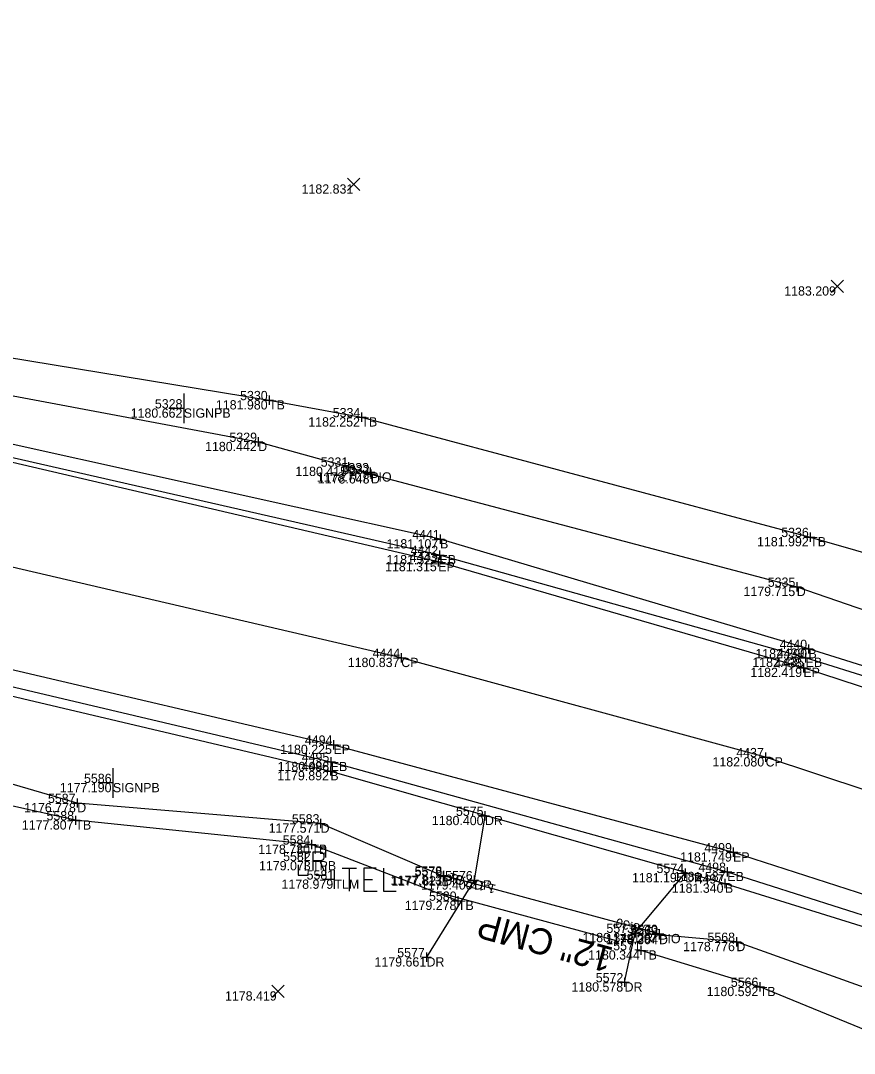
# Model space of a CAD drawing. Extents: x 2044996 to 2050343, y 455232 to 458054.
# Drawn here: x 2046920.1 to 2047010.1, y 457200 to 457311.5 of the extents above; entities that cross this region are included whole.
import ezdxf

# ---------------------------------------------------------------- set-up
doc = ezdxf.new("R2010")
doc.units = 0
for name, color, linetype in [('DR_X_Ditch', 7, 'Continuous'), ('DR_X_Elev_Flow', 7, 'Continuous'), ('DR_X_Storm_Sewer', 7, 'Continuous'), ('DR_X_Text', 7, 'Continuous'), ('DT_X_Contour_Minor', 7, 'Continuous'), ('DT_X_Contour_Text', 7, 'Continuous'), ('DT_X_Spot_Elev', 7, 'Continuous'), ('DT_X_TIN_Hull', 7, 'Continuous'), ('DT_X_Triangles', 7, 'Continuous'), ('DT_X_Void', 7, 'Continuous'), ('PV_X_COP', 7, 'Continuous'), ('PV_X_Driveway', 7, 'Continuous'), ('PV_X_EOP', 7, 'Continuous'), ('PV_X_Shoulder_Aggregate', 7, 'Continuous'), ('SC_Scratch1', 7, 'Continuous'), ('SG_X_PullBox', 7, 'Continuous'), ('SN_X_Public', 7, 'Continuous'), ('SV_X_Break_Lines', 7, 'Continuous'), ('SV_X_Top_of_Bank', 7, 'Continuous')]:
    doc.layers.add(name, color=color, linetype=linetype)

msp = doc.modelspace()

# ---------------------------------------------------------------- linework, layer by layer
at = {"layer": 'DR_X_Ditch'}
for points in [[(2046652.09, 457304.73), (2046697.72, 457300.76), (2046749.85, 457295.15), (2046773.58, 457293.27), (2046813.42, 457287.29), (2046865.63, 457279.49), (2046913.29, 457272.1), (2046945.7, 457266), (2046955.45, 457263.32), (2046957.87, 457262.51), (2047003.84, 457250.36), (2047016.8, 457245.89), (2047017.67, 457245.73), (2047064.32, 457227.1), (2047106.55, 457210.85), (2047146.99, 457194.6), (2047185.37, 457179.96), (2047230.91, 457162.64)], [(2046965.68, 457219.12), (2046952.44, 457224.82), (2046926.17, 457227.03), (2046902.99, 457233.78), (2046839.32, 457246.45), (2046782.21, 457253.65)], [(2047543.3, 457005.16), (2047510.9, 457017.43), (2047468.96, 457033.16), (2047427.45, 457048.41), (2047415.45, 457054.04), (2047370.9, 457068.47), (2047328.33, 457085.8), (2047280.45, 457104.21), (2047241.61, 457118.3), (2047187.46, 457140.33), (2047142.69, 457158.87), (2047125.5, 457162.21), (2047087.92, 457177.75), (2047044.55, 457195.18), (2046997.32, 457212.04), (2046988.97, 457212.79)]]:
    msp.add_lwpolyline(points, dxfattribs=at)
at = {"layer": 'DR_X_Elev_Flow'}
for p, q in [((2046957.8, 457263.22), (2046957.8, 457262.22)), ((2046957.3, 457262.72), (2046958.3, 457262.72)), ((2046957.8, 457262.72), (2046957.8, 457262.72)), ((2046965.7, 457219.7), (2046965.7, 457218.7)), ((2046965.2, 457219.2), (2046966.2, 457219.2)), ((2046965.7, 457219.2), (2046965.7, 457219.2)), ((2046988.49, 457212.9), (2046989.49, 457212.9)), ((2046988.99, 457213.4), (2046988.99, 457212.4)), ((2046988.99, 457212.9), (2046988.99, 457212.9))]:
    msp.add_line(p, q, dxfattribs=at)
at = {"layer": 'DR_X_Storm_Sewer'}
msp.add_line((2046988.99, 457212.9), (2046965.7, 457219.2), dxfattribs=at)
at = {"layer": 'DR_X_Text'}
msp.add_line((2046965.5, 457217.29), (2046984.34, 457212.19), dxfattribs=at)
at = {"layer": 'DT_X_Spot_Elev'}
for p, q in [((2046955.33, 457293.12), (2046956.67, 457294.46)), ((2046955.33, 457294.46), (2046956.67, 457293.12)), ((2047007.54, 457282.12), (2047008.88, 457283.46)), ((2047007.54, 457283.46), (2047008.88, 457282.12)), ((2046947.17, 457206.04), (2046948.5, 457207.38)), ((2046947.17, 457207.38), (2046948.5, 457206.04))]:
    msp.add_line(p, q, dxfattribs=at)
at = {"layer": 'DT_X_TIN_Hull'}
for p, q in [((2046953.93, 457217.77), (2046953.93, 457219.77)), ((2046953.93, 457218.77), (2046952.93, 457218.77))]:
    msp.add_line(p, q, dxfattribs=at)
for points in [[(2046954.75, 457220.01), (2046956.3, 457220.01)], [(2046955.53, 457220.01), (2046955.53, 457217.51)], [(2046958.45, 457220.01), (2046957.09, 457220.01), (2046957.09, 457217.51), (2046958.54, 457217.51)], [(2046959.23, 457220.01), (2046959.23, 457217.51), (2046960.59, 457217.51)], [(2046957.09, 457218.77), (2046958.05, 457218.77)]]:
    msp.add_lwpolyline(points, dxfattribs=at)
at = {"layer": 'DT_X_Void'}
for p, q in [((2046946.87, 457271), (2046946.87, 457270)), ((2046946.37, 457270.5), (2046947.37, 457270.5)), ((2046946.87, 457270.5), (2046946.87, 457270.5)), ((2046956.34, 457268.66), (2046957.34, 457268.66)), ((2046956.84, 457269.16), (2046956.84, 457268.16)), ((2046956.84, 457268.66), (2046956.84, 457268.66)), ((2046945.7, 457266.5), (2046945.7, 457265.5)), ((2046945.2, 457266), (2046946.2, 457266)), ((2046945.7, 457266), (2046945.7, 457266)), ((2046954.95, 457263.32), (2046955.95, 457263.32)), ((2046955.45, 457263.82), (2046955.45, 457262.82)), ((2046955.45, 457263.32), (2046955.45, 457263.32)), ((2046957.87, 457263.01), (2046957.87, 457262.01)), ((2046957.37, 457262.51), (2046958.37, 457262.51)), ((2046957.87, 457262.51), (2046957.87, 457262.51)), ((2046964.83, 457255.5), (2046965.83, 457255.5)), ((2046965.33, 457256), (2046965.33, 457255)), ((2046965.33, 457255.5), (2046965.33, 457255.5)), ((2047004.78, 457255.73), (2047005.78, 457255.73)), ((2047005.28, 457256.23), (2047005.28, 457255.23)), ((2047005.28, 457255.73), (2047005.28, 457255.73)), ((2046965.27, 457254.29), (2046965.27, 457253.29)), ((2046964.64, 457253.04), (2046965.64, 457253.04)), ((2046964.77, 457253.79), (2046965.77, 457253.79)), ((2046965.14, 457253.54), (2046965.14, 457252.54)), ((2046965.14, 457253.04), (2046965.14, 457253.04)), ((2046965.27, 457253.79), (2046965.27, 457253.79)), ((2047003.84, 457250.86), (2047003.84, 457249.86)), ((2047003.34, 457250.36), (2047004.34, 457250.36)), ((2047003.84, 457250.36), (2047003.84, 457250.36)), ((2047005.1, 457244.15), (2047005.1, 457243.15)), ((2046961.14, 457243.2), (2046961.14, 457242.2)), ((2047004.6, 457243.65), (2047005.6, 457243.65)), ((2047004.79, 457243.21), (2047004.79, 457242.21)), ((2047005.1, 457243.65), (2047005.1, 457243.65)), ((2046960.64, 457242.7), (2046961.64, 457242.7)), ((2046961.14, 457242.7), (2046961.14, 457242.7)), ((2047004.29, 457242.71), (2047005.29, 457242.71)), ((2047004.55, 457242.13), (2047004.55, 457241.13)), ((2047004.79, 457242.71), (2047004.79, 457242.71)), ((2047004.05, 457241.63), (2047005.05, 457241.63)), ((2047004.55, 457241.63), (2047004.55, 457241.63)), ((2046953.33, 457233.32), (2046954.33, 457233.32)), ((2046953.83, 457233.82), (2046953.83, 457232.82)), ((2046953.83, 457233.32), (2046953.83, 457233.32)), ((2046953.53, 457231.97), (2046953.53, 457230.97)), ((2046999.97, 457231.97), (2047000.97, 457231.97)), ((2047000.47, 457232.47), (2047000.47, 457231.47)), ((2047000.47, 457231.97), (2047000.47, 457231.97)), ((2046953.03, 457231.47), (2046954.03, 457231.47)), ((2046953.49, 457230.98), (2046953.49, 457229.98)), ((2046953.53, 457231.47), (2046953.53, 457231.47)), ((2046952.99, 457230.48), (2046953.99, 457230.48)), ((2046953.49, 457230.48), (2046953.49, 457230.48)), ((2046926.17, 457227.53), (2046926.17, 457226.53)), ((2046925.67, 457227.03), (2046926.67, 457227.03)), ((2046926.17, 457227.03), (2046926.17, 457227.03)), ((2046925.47, 457225.16), (2046926.47, 457225.16)), ((2046925.97, 457225.66), (2046925.97, 457224.66)), ((2046925.97, 457225.16), (2046925.97, 457225.16)), ((2046952.44, 457225.32), (2046952.44, 457224.32)), ((2046969.68, 457225.64), (2046970.68, 457225.64)), ((2046970.18, 457226.14), (2046970.18, 457225.14)), ((2046970.18, 457225.64), (2046970.18, 457225.64)), ((2046951.94, 457224.82), (2046952.94, 457224.82)), ((2046952.44, 457224.82), (2046952.44, 457224.82)), ((2046951.44, 457223.04), (2046951.44, 457222.04)), ((2046950.94, 457222.54), (2046951.94, 457222.54)), ((2046951.44, 457222.54), (2046951.44, 457222.54)), ((2046996.96, 457222.21), (2046996.96, 457221.21)), ((2046996.46, 457221.71), (2046997.46, 457221.71)), ((2046996.96, 457221.71), (2046996.96, 457221.71)), ((2046965.68, 457219.62), (2046965.68, 457218.62)), ((2046991.79, 457219.97), (2046991.79, 457218.97)), ((2046995.84, 457219.6), (2046996.84, 457219.6)), ((2046996.34, 457220.1), (2046996.34, 457219.1)), ((2046996.34, 457219.6), (2046996.34, 457219.6)), ((2046965.18, 457219.12), (2046966.18, 457219.12)), ((2046965.68, 457219.12), (2046965.68, 457219.12)), ((2046968.5, 457218.69), (2046969.5, 457218.69)), ((2046969, 457219.19), (2046969, 457218.19)), ((2046969, 457218.69), (2046969, 457218.69)), ((2046991.29, 457219.47), (2046992.29, 457219.47)), ((2046991.79, 457219.47), (2046991.79, 457219.47)), ((2046996.08, 457218.84), (2046996.08, 457217.84)), ((2046995.58, 457218.34), (2046996.58, 457218.34)), ((2046996.08, 457218.34), (2046996.08, 457218.34)), ((2046966.76, 457216.48), (2046967.76, 457216.48)), ((2046967.26, 457216.98), (2046967.26, 457215.98)), ((2046967.26, 457216.48), (2046967.26, 457216.48)), ((2046985.9, 457213.01), (2046986.9, 457213.01)), ((2046986.4, 457213.51), (2046986.4, 457212.51)), ((2046986.4, 457213.01), (2046986.4, 457213.01)), ((2046988.97, 457213.29), (2046988.97, 457212.29)), ((2046988.47, 457212.79), (2046989.47, 457212.79)), ((2046988.97, 457212.79), (2046988.97, 457212.79)), ((2046996.82, 457212.04), (2046997.82, 457212.04)), ((2046997.32, 457212.54), (2046997.32, 457211.54)), ((2046997.32, 457212.04), (2046997.32, 457212.04)), ((2046963.87, 457210.88), (2046963.87, 457209.88)), ((2046986.52, 457211.13), (2046987.52, 457211.13)), ((2046987.02, 457211.63), (2046987.02, 457210.63)), ((2046987.02, 457211.13), (2046987.02, 457211.13)), ((2046963.37, 457210.38), (2046964.37, 457210.38)), ((2046963.87, 457210.38), (2046963.87, 457210.38)), ((2046984.75, 457207.68), (2046985.75, 457207.68)), ((2046985.25, 457208.18), (2046985.25, 457207.18)), ((2046985.25, 457207.68), (2046985.25, 457207.68)), ((2046999.84, 457207.69), (2046999.84, 457206.69)), ((2046999.34, 457207.19), (2047000.34, 457207.19)), ((2046999.84, 457207.19), (2046999.84, 457207.19))]:
    msp.add_line(p, q, dxfattribs=at)
at = {"layer": 'PV_X_COP'}
msp.add_lwpolyline([(2047612.39, 456999.11), (2047580.09, 457011.53), (2047538.37, 457027.53), (2047496.01, 457043.83), (2047451.82, 457060.1), (2047409.77, 457076.51), (2047364.77, 457093.97), (2047313.94, 457114.01), (2047268.54, 457131.55), (2047222.12, 457149.92), (2047177.7, 457167.48), (2047132.78, 457184.84), (2047088.94, 457201.35), (2047045.02, 457217.22), (2047000.47, 457231.97), (2046961.14, 457242.7), (2046914.32, 457253.6), (2046869.82, 457261.81), (2046824.05, 457268.96), (2046778.68, 457274.62), (2046733.92, 457279.83), (2046684.61, 457284.92), (2046649.61, 457288.12)], dxfattribs=at)
at = {"layer": 'PV_X_Driveway'}
for points in [[(2046970.18, 457225.64), (2046969, 457218.69), (2046963.87, 457210.38)], [(2046985.25, 457207.68), (2046986.4, 457213.01), (2046991.79, 457219.47)]]:
    msp.add_lwpolyline(points, dxfattribs=at)
at = {"layer": 'PV_X_EOP'}
for p, q in [((2046965.14, 457253.04), (2046918.11, 457264.04)), ((2047004.55, 457241.63), (2046965.14, 457253.04)), ((2046911.24, 457243.27), (2046953.83, 457233.32)), ((2047049.38, 457226.95), (2047004.55, 457241.63)), ((2046953.83, 457233.32), (2046996.96, 457221.71)), ((2046996.96, 457221.71), (2047041.61, 457207.34))]:
    msp.add_line(p, q, dxfattribs=at)
at = {"layer": 'PV_X_Shoulder_Aggregate'}
for p, q in [((2046965.27, 457253.79), (2046918.09, 457264.54)), ((2047004.79, 457242.71), (2046965.27, 457253.79)), ((2047049.75, 457228.48), (2047004.79, 457242.71)), ((2046910.8, 457241.55), (2046953.53, 457231.47)), ((2046953.53, 457231.47), (2046996.34, 457219.6)), ((2046996.34, 457219.6), (2047041.53, 457205.14))]:
    msp.add_line(p, q, dxfattribs=at)
at = {"layer": 'SG_X_PullBox'}
msp.add_line((2046951.51, 457220.76), (2046951.51, 457220.76), dxfattribs=at)
for points in [[(2046951.11, 457222.26), (2046950.01, 457222.26), (2046950.01, 457221.16)], [(2046953.01, 457221.16), (2046953.01, 457222.26), (2046951.91, 457222.26)], [(2046950.15, 457221.76), (2046951.4, 457221.76)], [(2046950.78, 457221.76), (2046950.78, 457219.76)], [(2046951.62, 457219.76), (2046951.62, 457221.76), (2046952.38, 457221.76), (2046952.46, 457221.74), (2046952.57, 457221.71), (2046952.61, 457221.68), (2046952.66, 457221.65), (2046952.72, 457221.57), (2046952.77, 457221.49), (2046952.8, 457221.36), (2046952.8, 457221.18), (2046952.79, 457221.11), (2046952.75, 457221.02), (2046952.69, 457220.91), (2046952.63, 457220.86), (2046952.58, 457220.83), (2046952.55, 457220.81), (2046952.5, 457220.8), (2046952.36, 457220.78), (2046951.62, 457220.78)], [(2046952.36, 457220.78), (2046952.8, 457219.76)], [(2046950.01, 457220.36), (2046950.01, 457219.26), (2046951.11, 457219.26)], [(2046951.91, 457219.26), (2046953.01, 457219.26), (2046953.01, 457220.36)]]:
    msp.add_lwpolyline(points, dxfattribs=at)
at = {"layer": 'SN_X_Public'}
for p, q in [((2046937.67, 457271.21), (2046937.67, 457268.01)), ((2046937.67, 457269.61), (2046936.07, 457269.61)), ((2046930.02, 457230.79), (2046930.02, 457227.59)), ((2046930.02, 457229.19), (2046928.42, 457229.19))]:
    msp.add_line(p, q, dxfattribs=at)
at = {"layer": 'SV_X_Break_Lines'}
for points in [[(2047227.37, 457161.69), (2047183.55, 457178.86), (2047137.31, 457196.49), (2047094.49, 457213.08), (2047049.99, 457229.63), (2047005.1, 457243.65), (2046965.33, 457255.5), (2046918.59, 457265.88), (2046873.66, 457274.63), (2046827.67, 457281.56), (2046780.24, 457288.39), (2046735.28, 457292.81), (2046686.23, 457298.46), (2046651.06, 457301.99)], [(2046644.99, 457274.79), (2046684.79, 457271.32), (2046731.45, 457265.98), (2046776.36, 457261.92), (2046820.97, 457255.96), (2046865.17, 457248.93), (2046910.62, 457240.57), (2046953.49, 457230.48), (2046996.08, 457218.34), (2047041.05, 457204.36), (2047086.23, 457188.11), (2047130.38, 457171.33), (2047171.93, 457154.51), (2047216.75, 457137.04), (2047260.77, 457120.17), (2047304.38, 457102.94), (2047349.36, 457085.13), (2047391.24, 457069.28), (2047438.05, 457051.14), (2047480.2, 457035.91), (2047522.53, 457019.68), (2047543.14, 457011.06)]]:
    msp.add_lwpolyline(points, dxfattribs=at)
at = {"layer": 'SV_X_Top_of_Bank'}
for points in [[(2046651.93, 457311.46), (2046700.58, 457305.72), (2046746.85, 457300.37), (2046773.13, 457296.21), (2046810.21, 457291.65), (2046866.31, 457282.87), (2046913.13, 457276.05), (2046946.87, 457270.5), (2046956.84, 457268.66), (2047005.28, 457255.73), (2047019.97, 457251.51), (2047064.03, 457231.46), (2047107.63, 457215.29), (2047146.99, 457200.96), (2047188.63, 457185.75), (2047229.81, 457169.99), (2047277.5, 457150.03), (2047328.36, 457129.78), (2047359.21, 457118.11), (2047442.14, 457085.97), (2047488.03, 457067.35), (2047530.83, 457050.42), (2047563.67, 457038.95)], [(2046967.26, 457216.48), (2046951.44, 457222.54), (2046925.97, 457225.16), (2046902.29, 457230.46), (2046839.85, 457240.52), (2046781.98, 457251.18)], [(2047542.15, 457001.74), (2047509.52, 457012.3), (2047466.73, 457029.21), (2047424.59, 457044.27), (2047411.67, 457048.03), (2047368.41, 457063.9), (2047324.9, 457081.08), (2047276.68, 457098.42), (2047234.84, 457112.37), (2047186.92, 457131.46), (2047138.32, 457152.85), (2047124.48, 457159.14), (2047084.84, 457174.36), (2047041.82, 457189.99), (2046999.84, 457207.19), (2046987.02, 457211.13)]]:
    msp.add_lwpolyline(points, dxfattribs=at)

# ---------------------------------------------------------------- texts
at = {"layer": 'DR_X_Text'}
msp.add_text('12" CMP', height=2.8, rotation=164.8651, dxfattribs=at).set_placement((2046984.19, 457211.38))
at = {"layer": 'DT_X_Contour_Minor'}
for s, p in [('1182.831', (2046950.39, 457292.79)), ('1183.209', (2047002.49, 457281.79)), ('1181.980', (2046941.14, 457269.5)), ('1180.662', (2046931.94, 457268.61)), ('1182.252', (2046951.11, 457267.66)), ('1180.442', (2046939.97, 457265)), ('1180.415', (2046949.71, 457262.32)), ('1178.707', (2046952.02, 457261.72)), ('1178.648', (2046952.14, 457261.51)), ('1181.107', (2046959.56, 457254.5)), ('1181.992', (2046999.55, 457254.73)), ('1181.315', (2046959.4, 457252.04)), ('1181.322', (2046959.54, 457252.79)), ('1179.715', (2046998.09, 457249.36)), ('1182.290', (2046999.37, 457242.65)), ('1180.837', (2046955.37, 457241.7)), ('1182.435', (2046999.04, 457241.71)), ('1182.419', (2046998.83, 457240.63)), ('1180.225', (2046948.08, 457232.32)), ('1182.080', (2046994.74, 457230.97)), ('1180.088', (2046947.8, 457230.47)), ('1179.892', (2046947.76, 457229.48)), ('1177.190', (2046924.29, 457228.19)), ('1176.778', (2046920.44, 457226.03)), ('1177.807', (2046920.19, 457224.16)), ('1180.400', (2046964.45, 457224.64)), ('1177.571', (2046946.83, 457223.82)), ('1178.730', (2046945.71, 457221.54)), ('1179.073', (2046945.79, 457219.76)), ('1181.749', (2046991.25, 457220.71)), ('1181.587', (2046990.57, 457218.6)), ('1178.979', (2046948.22, 457217.77)), ('1177.813', (2046959.98, 457218.2)), ('1177.821', (2046960.07, 457218.12)), ('1179.400', (2046963.27, 457217.69)), ('1181.195', (2046986.05, 457218.47)), ('1181.340', (2046990.35, 457217.34)), ('1179.278', (2046961.52, 457215.48)), ('1180.344', (2046980.7, 457212.01)), ('1178.297', (2046983.22, 457211.9)), ('1178.304', (2046983.27, 457211.79)), ('1178.776', (2046991.58, 457211.04)), ('1180.344', (2046981.32, 457210.13)), ('1179.661', (2046958.26, 457209.38)), ('1180.578', (2046979.52, 457206.68)), ('1178.419', (2046942.12, 457205.71)), ('1180.592', (2046994.11, 457206.19))]:
    msp.add_text(s, height=1, dxfattribs=at).set_placement(p)
at = {"layer": 'DT_X_Contour_Text'}
for s, p in [('TB', (2046946.87, 457269.5)), ('SIGNPB', (2046937.67, 457268.61)), ('TB', (2046956.84, 457267.66)), ('D', (2046945.7, 457265)), ('D', (2046955.45, 457262.32)), ('PIO', (2046957.8, 457261.72)), ('D', (2046957.87, 457261.51)), ('B', (2046965.33, 457254.5)), ('TB', (2047005.28, 457254.73)), ('EP', (2046965.14, 457252.04)), ('EB', (2046965.27, 457252.79)), ('D', (2047003.84, 457249.36)), ('B', (2047005.1, 457242.65)), ('CP', (2046961.14, 457241.7)), ('EB', (2047004.79, 457241.71)), ('EP', (2047004.55, 457240.63)), ('EP', (2046953.83, 457232.32)), ('CP', (2047000.47, 457230.97)), ('EB', (2046953.53, 457230.47)), ('B', (2046953.49, 457229.48)), ('SIGNPB', (2046930.02, 457228.19)), ('D', (2046926.17, 457226.03)), ('TB', (2046925.97, 457224.16)), ('DR', (2046970.18, 457224.64)), ('D', (2046952.44, 457223.82)), ('TB', (2046951.44, 457221.54)), ('TPB', (2046951.51, 457219.76)), ('EP', (2046996.96, 457220.71)), ('EB', (2046996.34, 457218.6)), ('TLM', (2046953.93, 457217.77)), ('D', (2046965.68, 457218.12)), ('PIO', (2046965.7, 457218.2)), ('DR', (2046969, 457217.69)), ('DR', (2046991.79, 457218.47)), ('B', (2046996.08, 457217.34)), ('TB', (2046967.26, 457215.48)), ('DR', (2046986.4, 457212.01)), ('PIO', (2046988.99, 457211.9)), ('D', (2046988.97, 457211.79)), ('D', (2046997.32, 457211.04)), ('TB', (2046987.02, 457210.13)), ('DR', (2046963.87, 457209.38)), ('DR', (2046985.25, 457206.68)), ('TB', (2046999.84, 457206.19))]:
    msp.add_text(s, height=1, dxfattribs=at).set_placement(p)
at = {"layer": 'DT_X_Triangles'}
for s, p in [('5330', (2046943.75, 457270.5)), ('5328', (2046934.55, 457269.61)), ('5334', (2046953.75, 457268.66)), ('5329', (2046942.6, 457266)), ('5331', (2046952.45, 457263.32)), ('5333', (2046954.69, 457262.72)), ('5332', (2046954.76, 457262.51)), ('4441', (2046962.33, 457255.5)), ('5336', (2047002.16, 457255.73)), ('4442', (2046962.15, 457253.79)), ('4443', (2046962.04, 457253.04)), ('5335', (2047000.71, 457250.36)), ('4440', (2047001.98, 457243.65)), ('4444', (2046958.05, 457242.7)), ('4439', (2047001.69, 457242.71)), ('4438', (2047001.43, 457241.63)), ('4494', (2046950.74, 457233.32)), ('4437', (2046997.31, 457231.97)), ('4495', (2046950.4, 457231.47)), ('4496', (2046950.37, 457230.48)), ('5586', (2046926.9, 457229.19)), ('5587', (2046923.01, 457227.03)), ('5575', (2046967.05, 457225.64)), ('5588', (2046922.85, 457225.16)), ('5583', (2046949.34, 457224.82)), ('5584', (2046948.35, 457222.54)), ('5582', (2046948.39, 457220.76)), ('4499', (2046993.86, 457221.71)), ('5581', (2046950.93, 457218.77)), ('5579', (2046962.58, 457219.12)), ('5578', (2046962.59, 457219.2)), ('5576', (2046965.88, 457218.69)), ('5574', (2046988.7, 457219.47)), ('4498', (2046993.22, 457219.6)), ('4497', (2046992.92, 457218.34)), ('5580', (2046964.14, 457216.48)), ('5573', (2046983.29, 457213.01)), ('5570', (2046985.87, 457212.9)), ('5569', (2046985.87, 457212.79)), ('5568', (2046994.2, 457212.04)), ('5571', (2046984.02, 457211.13)), ('5577', (2046960.71, 457210.38)), ('5572', (2046982.14, 457207.68)), ('5566', (2046996.72, 457207.19))]:
    msp.add_text(s, height=1, dxfattribs=at).set_placement(p)
at = {"layer": 'SC_Scratch1'}
for s, p in [("1,177.81'", (2046971.43, 457218.17)), ("1178.30'", (2046989.12, 457213.38))]:
    msp.add_text(s, height=1, rotation=164.8651, dxfattribs=at).set_placement(p)

doc.saveas('drawing.dxf')
